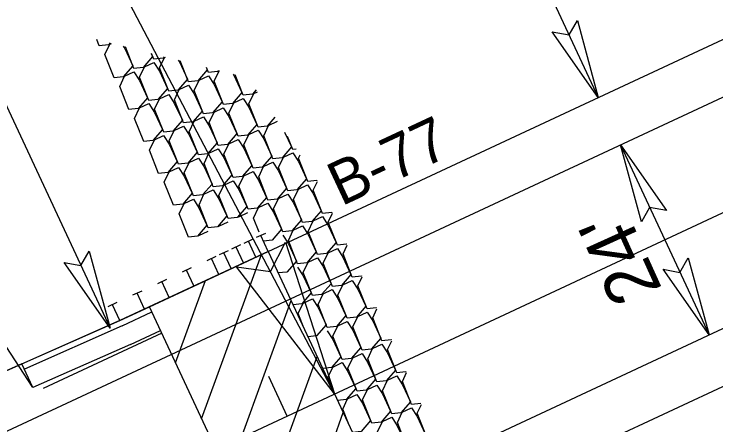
# Model space of a CAD drawing. Extents: x 2320644 to 2322941, y 921672 to 923041.
# Drawn here: x 2321563.6 to 2321644, y 922163 to 922210 of the extents above; entities that cross this region are included whole.
import ezdxf

# ---------------------------------------------------------------- set-up
doc = ezdxf.new("R2010")
doc.units = 0
for name, color, linetype in [('Matchline', 7, 'Continuous'), ('Prop Approach Slab', 7, 'Continuous'), ('Prop Approach Slab Hatching', 7, 'Continuous'), ('Prop Conc Shoulder Berm Gutter', 7, 'Continuous'), ('Prop EOT', 7, 'Continuous'), ('Prop Guardrail', 7, 'Continuous'), ('Prop Horizontal Alignment Tick Large', 7, 'Continuous'), ('Prop Horizontal Alignment Tick Small', 7, 'Continuous'), ('Prop North Arrow NAD83 for Plan Sheets CELL', 7, 'Continuous'), ('Prop Structure Anchor Unit CELL', 7, 'Continuous'), ('Sheet Profile Grid Major CELL', 7, 'Continuous'), ('Sheet Profile Grid Minor CELL', 7, 'Continuous'), ('Sheet Sticker Exception Certification CELL', 7, 'Continuous'), ('Skimmer Basin Note Both CELL', 7, 'Continuous')]:
    doc.layers.add(name, color=color, linetype=linetype)

msp = doc.modelspace()

# ---------------------------------------------------------------- linework, layer by layer
at = {"layer": 'Matchline'}
msp.add_line((2321411.134, 922078.361), (2321804.398, 922261.67), dxfattribs=at)
at = {"layer": 'Prop Approach Slab'}
for p, q in [((2321406.064, 922089.237), (2321799.328, 922272.547)), ((2321416.203, 922067.484), (2321809.467, 922250.794)), ((2321579.089, 922176.508), (2321592.685, 922182.845)), ((2321594.298, 922143.879), (2321579.089, 922176.508))]:
    msp.add_line(p, q, dxfattribs=at)
at = {"layer": 'Prop Approach Slab Hatching'}
for p, q in [((2321585.064, 922163.69), (2321591.907, 922182.483)), ((2321582.076, 922170.099), (2321585.498, 922179.495)), ((2321588.051, 922157.281), (2321595.31, 922177.214)), ((2321591.039, 922150.872), (2321598.297, 922170.805)), ((2321594.026, 922144.463), (2321601.284, 922164.396))]:
    msp.add_line(p, q, dxfattribs=at)
at = {"layer": 'Prop Conc Shoulder Berm Gutter'}
for p, q in [((2321576.93, 922172.192), (2321580.356, 922173.789)), ((2321576.93, 922172.192), (2321565.752, 922167.251)), ((2321564.484, 922169.971), (2321484.208, 922134.488)), ((2321565.752, 922167.251), (2321564.484, 922169.971))]:
    msp.add_line(p, q, dxfattribs=at)
at = {"layer": 'Prop Guardrail'}
msp.add_line((2321575.69, 922174.924), (2321484.208, 922134.488), dxfattribs=at)
at = {"layer": 'Prop Horizontal Alignment Tick Large'}
for p, q in [((2321592.685, 922182.845), (2321783.023, 922271.566)), ((2321607.894, 922150.216), (2321798.232, 922238.937)), ((2321592.685, 922182.845), (2321607.894, 922150.216))]:
    msp.add_line(p, q, dxfattribs=at)
at = {"layer": 'Prop Horizontal Alignment Tick Small'}
msp.add_line((2321594.851, 922163.996), (2321592.739, 922168.527), dxfattribs=at)
at = {"layer": 'Prop North Arrow NAD83 for Plan Sheets CELL'}
for p, q in [((2321600.289, 922166.53), (2321523.789, 922312.144)), ((2321565.752, 922167.251), (2321509.774, 922252.575)), ((2321619.024, 922225.021), (2321630.485, 922200.465)), ((2321633.022, 922195.028), (2321643.172, 922173.28))]:
    msp.add_line(p, q, dxfattribs=at)
at = {"layer": 'Prop Structure Anchor Unit CELL'}
for p, q in [((2321592.359, 922184.9), (2321591.32, 922184.416)), ((2321592.685, 922182.845), (2321591.84, 922184.658)), ((2321590.943, 922184.24), (2321589.904, 922183.756)), ((2321591.268, 922182.185), (2321590.423, 922183.998)), ((2321592.685, 922182.845), (2321575.69, 922174.924)), ((2321588.11, 922182.92), (2321587.072, 922182.436)), ((2321589.526, 922183.58), (2321588.488, 922183.096)), ((2321589.852, 922181.525), (2321589.007, 922183.338)), ((2321586.694, 922182.259), (2321585.656, 922181.775)), ((2321587.02, 922180.205), (2321586.175, 922182.017)), ((2321588.436, 922180.865), (2321587.591, 922182.678)), ((2321583.861, 922180.939), (2321582.823, 922180.455)), ((2321584.187, 922178.884), (2321583.342, 922180.697)), ((2321581.029, 922179.619), (2321579.991, 922179.135)), ((2321581.355, 922177.564), (2321580.51, 922179.377)), ((2321578.197, 922178.299), (2321577.158, 922177.815)), ((2321578.523, 922176.244), (2321577.678, 922178.057)), ((2321575.364, 922176.978), (2321574.326, 922176.494)), ((2321575.69, 922174.924), (2321574.845, 922176.736))]:
    msp.add_line(p, q, dxfattribs=at)
at = {"layer": 'Sheet Profile Grid Major CELL'}
for points in [[(2321574.577, 922206.696), (2321574.387, 922206.478), (2321573.338, 922206.361), (2321573.05, 922207.083)], [(2321576.085, 922206.314), (2321576.254, 922206.052), (2321577.173, 922204.08), (2321576.088, 922202.829), (2321575.039, 922202.713), (2321573.982, 922205.365), (2321574.546, 922206.551), (2321574.758, 922206.65)], [(2321579.282, 922205.503), (2321579.451, 922205.142), (2321578.365, 922203.891), (2321577.316, 922203.774), (2321576.329, 922206.252)], [(2321580.788, 922205.121), (2321580.642, 922204.952), (2321579.593, 922204.836), (2321579.332, 922205.49)], [(2321582.387, 922204.715), (2321582.509, 922204.526), (2321583.428, 922202.555), (2321582.343, 922201.304), (2321581.294, 922201.188), (2321580.237, 922203.839), (2321580.801, 922205.026), (2321580.928, 922205.086)], [(2321585.57, 922203.908), (2321585.706, 922203.617), (2321584.62, 922202.366), (2321583.571, 922202.249), (2321582.611, 922204.659)], [(2321579.589, 922204.461), (2321580.232, 922203.465), (2321581.151, 922201.494), (2321580.065, 922200.243), (2321579.016, 922200.126), (2321577.96, 922202.778), (2321578.524, 922203.965), (2321579.589, 922204.461)], [(2321587, 922203.546), (2321586.897, 922203.427), (2321585.848, 922203.311), (2321585.615, 922203.897)], [(2321577.311, 922203.4), (2321577.955, 922202.403), (2321578.874, 922200.432), (2321577.788, 922199.181), (2321576.739, 922199.065), (2321575.682, 922201.716), (2321576.246, 922202.903), (2321577.311, 922203.4)], [(2321585.844, 922202.936), (2321586.487, 922201.94), (2321587.406, 922199.968), (2321586.32, 922198.718), (2321585.271, 922198.601), (2321584.215, 922201.253), (2321584.779, 922202.44), (2321585.844, 922202.936)], [(2321588.69, 922203.117), (2321588.764, 922203.001), (2321589.683, 922201.03), (2321588.598, 922199.779), (2321587.549, 922199.662), (2321586.492, 922202.314), (2321587.056, 922203.501), (2321587.098, 922203.521)], [(2321591.316, 922201.348), (2321590.875, 922200.841), (2321589.826, 922200.724), (2321588.893, 922203.066)], [(2321583.566, 922201.875), (2321584.21, 922200.878), (2321585.129, 922198.907), (2321584.043, 922197.656), (2321582.994, 922197.539), (2321581.937, 922200.191), (2321582.501, 922201.378), (2321583.566, 922201.875)], [(2321581.289, 922200.813), (2321581.933, 922199.817), (2321582.852, 922197.845), (2321581.766, 922196.595), (2321580.717, 922196.478), (2321579.66, 922199.13), (2321580.224, 922200.317), (2321581.289, 922200.813)], [(2321593.437, 922198.185), (2321592.575, 922197.192), (2321591.526, 922197.076), (2321590.47, 922199.728), (2321591.034, 922200.914), (2321591.47, 922201.118)], [(2321579.012, 922199.752), (2321579.655, 922198.755), (2321580.574, 922196.784), (2321579.489, 922195.533), (2321578.44, 922195.417), (2321577.383, 922198.068), (2321577.947, 922199.255), (2321579.012, 922199.752)], [(2321589.821, 922200.349), (2321590.465, 922199.353), (2321591.384, 922197.382), (2321590.298, 922196.131), (2321589.249, 922196.014), (2321588.192, 922198.666), (2321588.756, 922199.853), (2321589.821, 922200.349)], [(2321587.544, 922199.288), (2321588.188, 922198.292), (2321589.107, 922196.32), (2321588.021, 922195.069), (2321586.972, 922194.953), (2321585.915, 922197.605), (2321586.479, 922198.791), (2321587.544, 922199.288)], [(2321585.267, 922198.226), (2321585.91, 922197.23), (2321586.829, 922195.259), (2321585.744, 922194.008), (2321584.695, 922193.891), (2321583.638, 922196.543), (2321584.202, 922197.73), (2321585.267, 922198.226)], [(2321594.567, 922196.499), (2321595.362, 922194.795), (2321594.276, 922193.544), (2321593.227, 922193.428), (2321592.17, 922196.079), (2321592.734, 922197.266), (2321593.739, 922197.735)], [(2321582.99, 922197.165), (2321583.633, 922196.169), (2321584.552, 922194.197), (2321583.466, 922192.946), (2321582.417, 922192.83), (2321581.361, 922195.482), (2321581.925, 922196.669), (2321582.99, 922197.165)], [(2321591.522, 922196.701), (2321592.165, 922195.705), (2321593.084, 922193.734), (2321591.999, 922192.483), (2321590.95, 922192.366), (2321589.893, 922195.018), (2321590.457, 922196.205), (2321591.522, 922196.701)], [(2321580.712, 922196.103), (2321581.356, 922195.107), (2321582.275, 922193.136), (2321581.189, 922191.885), (2321580.14, 922191.768), (2321579.083, 922194.42), (2321579.647, 922195.607), (2321580.712, 922196.103)], [(2321595.887, 922194.532), (2321595.504, 922194.489), (2321594.902, 922195.999)], [(2321589.245, 922195.64), (2321589.888, 922194.643), (2321590.807, 922192.672), (2321589.721, 922191.421), (2321588.672, 922191.305), (2321587.616, 922193.956), (2321588.18, 922195.143), (2321589.245, 922195.64)], [(2321586.967, 922194.578), (2321587.611, 922193.582), (2321588.53, 922191.611), (2321587.444, 922190.36), (2321586.395, 922190.243), (2321585.338, 922192.895), (2321585.902, 922194.082), (2321586.967, 922194.578)], [(2321595.5, 922194.115), (2321596.143, 922193.118), (2321597.062, 922191.147), (2321595.976, 922189.896), (2321594.927, 922189.78), (2321593.871, 922192.431), (2321594.435, 922193.618), (2321595.5, 922194.115)], [(2321584.69, 922193.517), (2321585.334, 922192.52), (2321586.253, 922190.549), (2321585.167, 922189.298), (2321584.118, 922189.182), (2321583.061, 922191.834), (2321583.625, 922193.02), (2321584.69, 922193.517)], [(2321598.27, 922190.977), (2321598.254, 922190.958), (2321597.205, 922190.841), (2321596.148, 922193.493), (2321596.328, 922193.873)], [(2321593.222, 922193.053), (2321593.866, 922192.057), (2321594.785, 922190.085), (2321593.699, 922188.835), (2321592.65, 922188.718), (2321591.593, 922191.37), (2321592.157, 922192.557), (2321593.222, 922193.053)], [(2321582.413, 922192.455), (2321583.056, 922191.459), (2321583.975, 922189.488), (2321582.89, 922188.237), (2321581.841, 922188.12), (2321580.784, 922190.772), (2321581.348, 922191.959), (2321582.413, 922192.455)], [(2321590.945, 922191.992), (2321591.589, 922190.995), (2321592.508, 922189.024), (2321591.422, 922187.773), (2321590.373, 922187.657), (2321589.316, 922190.308), (2321589.88, 922191.495), (2321590.945, 922191.992)], [(2321588.668, 922190.93), (2321589.311, 922189.934), (2321590.23, 922187.962), (2321589.145, 922186.712), (2321588.096, 922186.595), (2321587.039, 922189.247), (2321587.603, 922190.434), (2321588.668, 922190.93)], [(2321599.972, 922187.33), (2321599.954, 922187.309), (2321598.905, 922187.193), (2321597.848, 922189.845), (2321598.329, 922190.856)], [(2321597.2, 922190.466), (2321597.844, 922189.47), (2321598.763, 922187.499), (2321597.677, 922186.248), (2321596.628, 922186.131), (2321595.571, 922188.783), (2321596.135, 922189.97), (2321597.2, 922190.466)], [(2321586.39, 922189.869), (2321587.034, 922188.872), (2321587.953, 922186.901), (2321586.867, 922185.65), (2321585.818, 922185.534), (2321584.762, 922188.185), (2321585.325, 922189.372), (2321586.39, 922189.869)], [(2321594.923, 922189.405), (2321595.566, 922188.409), (2321596.485, 922186.437), (2321595.4, 922185.186), (2321594.351, 922185.07), (2321593.294, 922187.722), (2321593.858, 922188.909), (2321594.923, 922189.405)], [(2321584.113, 922188.807), (2321584.757, 922187.811), (2321585.676, 922185.839), (2321584.59, 922184.589), (2321583.541, 922184.472), (2321582.484, 922187.124), (2321583.048, 922188.311), (2321584.113, 922188.807)], [(2321591.667, 922185.028), (2321591.017, 922186.66), (2321591.58, 922187.847), (2321592.645, 922188.343)], [(2321592.645, 922188.343), (2321593.289, 922187.347), (2321594.208, 922185.376), (2321593.122, 922184.125), (2321592.139, 922184.016)], [(2321589.303, 922186.786), (2321589.303, 922186.786), (2321590.368, 922187.282)], [(2321601.673, 922183.682), (2321601.655, 922183.661), (2321600.606, 922183.545), (2321599.549, 922186.197), (2321600.029, 922187.208)], [(2321587.026, 922185.724), (2321587.026, 922185.724), (2321588.091, 922186.221)], [(2321598.9, 922186.818), (2321599.544, 922185.822), (2321600.463, 922183.851), (2321599.377, 922182.6), (2321598.328, 922182.483), (2321597.272, 922185.135), (2321597.835, 922186.322), (2321598.9, 922186.818)], [(2321596.623, 922185.757), (2321597.267, 922184.76), (2321598.186, 922182.789), (2321597.1, 922181.538), (2321596.051, 922181.422), (2321594.994, 922184.074), (2321595.558, 922185.26), (2321596.623, 922185.757)], [(2321584.749, 922184.663), (2321584.749, 922184.663), (2321585.814, 922185.159)], [(2321594.346, 922184.695), (2321594.99, 922183.699), (2321595.909, 922181.728), (2321594.823, 922180.477), (2321593.839, 922180.368)], [(2321600.601, 922183.17), (2321601.245, 922182.174), (2321602.164, 922180.202), (2321601.078, 922178.952), (2321600.029, 922178.835), (2321598.972, 922181.487), (2321599.536, 922182.674), (2321600.601, 922183.17)], [(2321603.373, 922180.034), (2321603.355, 922180.013), (2321602.306, 922179.897), (2321601.249, 922182.548), (2321601.73, 922183.559)], [(2321598.324, 922182.109), (2321598.967, 922181.112), (2321599.886, 922179.141), (2321598.801, 922177.89), (2321597.752, 922177.774), (2321596.695, 922180.425), (2321597.259, 922181.612), (2321598.324, 922182.109)], [(2321596.046, 922181.047), (2321596.69, 922180.051), (2321597.609, 922178.079), (2321596.523, 922176.829), (2321595.54, 922176.719)], [(2321605.074, 922176.386), (2321605.056, 922176.365), (2321604.007, 922176.248), (2321602.95, 922178.9), (2321603.43, 922179.911)], [(2321602.301, 922179.522), (2321602.945, 922178.526), (2321603.864, 922176.554), (2321602.778, 922175.303), (2321601.729, 922175.187), (2321600.673, 922177.839), (2321601.236, 922179.026), (2321602.301, 922179.522)], [(2321600.024, 922178.461), (2321600.668, 922177.464), (2321601.587, 922175.493), (2321600.501, 922174.242), (2321599.452, 922174.125), (2321598.395, 922176.777), (2321598.959, 922177.964), (2321600.024, 922178.461)], [(2321596.768, 922174.084), (2321596.118, 922175.716), (2321596.682, 922176.903), (2321597.747, 922177.399)], [(2321597.747, 922177.399), (2321598.391, 922176.403), (2321599.31, 922174.431), (2321598.224, 922173.181), (2321597.24, 922173.071)], [(2321604.002, 922175.874), (2321604.646, 922174.878), (2321605.565, 922172.906), (2321604.479, 922171.655), (2321603.43, 922171.539), (2321602.373, 922174.191), (2321602.937, 922175.377), (2321604.002, 922175.874)], [(2321606.774, 922172.738), (2321606.756, 922172.717), (2321605.707, 922172.6), (2321604.65, 922175.252), (2321605.131, 922176.263)], [(2321601.725, 922174.812), (2321602.368, 922173.816), (2321603.287, 922171.845), (2321602.202, 922170.594), (2321601.153, 922170.477), (2321600.096, 922173.129), (2321600.66, 922174.316), (2321601.725, 922174.812)], [(2321599.447, 922173.751), (2321600.091, 922172.755), (2321601.01, 922170.783), (2321599.924, 922169.532), (2321598.941, 922169.423)], [(2321608.475, 922169.089), (2321608.457, 922169.069), (2321607.408, 922168.952), (2321606.351, 922171.604), (2321606.831, 922172.615)], [(2321605.702, 922172.226), (2321606.346, 922171.229), (2321607.265, 922169.258), (2321606.179, 922168.007), (2321605.13, 922167.891), (2321604.074, 922170.542), (2321604.637, 922171.729), (2321605.702, 922172.226)], [(2321603.425, 922171.164), (2321604.069, 922170.168), (2321604.988, 922168.197), (2321603.902, 922166.946), (2321602.853, 922166.829), (2321601.796, 922169.481), (2321602.36, 922170.668), (2321603.425, 922171.164)], [(2321600.169, 922166.788), (2321599.519, 922168.419), (2321600.083, 922169.606), (2321601.148, 922170.103)], [(2321601.148, 922170.103), (2321601.792, 922169.106), (2321602.71, 922167.135), (2321601.625, 922165.884), (2321600.641, 922165.775)], [(2321607.403, 922168.578), (2321608.047, 922167.581), (2321608.965, 922165.61), (2321607.88, 922164.359), (2321606.831, 922164.242), (2321605.774, 922166.894), (2321606.338, 922168.081), (2321607.403, 922168.578)], [(2321610.175, 922165.441), (2321610.157, 922165.421), (2321609.108, 922165.304), (2321608.051, 922167.956), (2321608.532, 922168.967)], [(2321605.126, 922167.516), (2321605.769, 922166.52), (2321606.688, 922164.548), (2321605.603, 922163.298), (2321604.554, 922163.181), (2321603.497, 922165.833), (2321604.061, 922167.02), (2321605.126, 922167.516)], [(2321601.87, 922163.139), (2321601.22, 922164.771), (2321601.783, 922165.958), (2321602.848, 922166.455)], [(2321602.848, 922166.455), (2321603.492, 922165.458), (2321604.411, 922163.487), (2321603.325, 922162.236), (2321602.342, 922162.127)], [(2321611.875, 922161.793), (2321611.858, 922161.772), (2321610.809, 922161.656), (2321609.752, 922164.308), (2321610.232, 922165.319)], [(2321609.103, 922164.929), (2321609.747, 922163.933), (2321610.666, 922161.962), (2321609.58, 922160.711), (2321608.531, 922160.594), (2321607.475, 922163.246), (2321608.038, 922164.433), (2321609.103, 922164.929)], [(2321606.826, 922163.868), (2321607.47, 922162.872), (2321608.389, 922160.9), (2321607.303, 922159.649), (2321606.254, 922159.533), (2321605.197, 922162.185), (2321605.761, 922163.372), (2321606.826, 922163.868)]]:
    msp.add_lwpolyline(points, dxfattribs=at)
at = {"layer": 'Sheet Profile Grid Minor CELL'}
for p, q in [((2321545.832, 922235.65), (2321574.58, 922174.053)), ((2321580.496, 922173.49), (2321566.9, 922167.153))]:
    msp.add_line(p, q, dxfattribs=at)
msp.add_lwpolyline([(2321572.178, 922182.864), (2321574.58, 922174.053), (2321569.303, 922181.577), (2321571.239, 922181.211)], close=True, dxfattribs=at)
at = {"layer": 'Sheet Sticker Exception Certification CELL'}
for points in [[(2321628.083, 922209.276), (2321630.485, 922200.465), (2321625.207, 922207.989), (2321627.144, 922207.623)], [(2321635.424, 922186.217), (2321633.022, 922195.028), (2321638.299, 922187.504), (2321636.363, 922187.869)], [(2321594.664, 922183.908), (2321600.289, 922166.53), (2321589.04, 922181.067), (2321592.943, 922180.519)], [(2321640.77, 922182.091), (2321643.172, 922173.28), (2321637.895, 922180.804), (2321639.831, 922180.438)]]:
    msp.add_lwpolyline(points, close=True, dxfattribs=at)
at = {"layer": 'Skimmer Basin Note Both CELL'}
for p, q in [((2321575.69, 922174.924), (2321579.089, 922176.508)), ((2321575.966, 922174.317), (2321579.371, 922175.904)), ((2321564.484, 922169.971), (2321575.69, 922174.924)), ((2321575.966, 922174.317), (2321564.766, 922169.366))]:
    msp.add_line(p, q, dxfattribs=at)

# ---------------------------------------------------------------- texts
at = {"layer": 'Prop EOT'}
msp.add_text('B-77', height=5, rotation=25.01869, dxfattribs=at).set_placement((2321601.05, 922187.967))
at = {"layer": 'Prop North Arrow NAD83 for Plan Sheets CELL'}
msp.add_text("24'", height=6, rotation=114.34158, dxfattribs=at).set_placement((2321637.837, 922178.51))

doc.saveas('drawing.dxf')
